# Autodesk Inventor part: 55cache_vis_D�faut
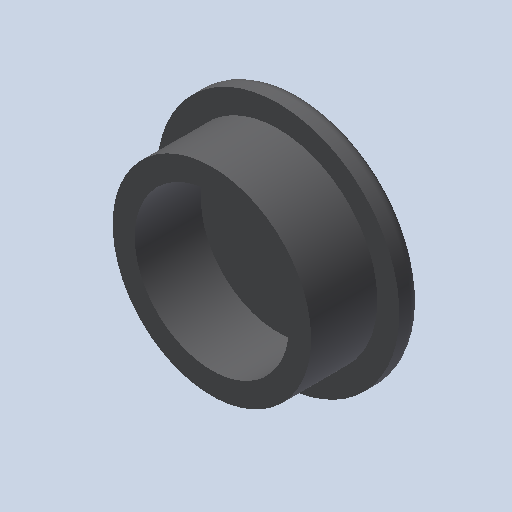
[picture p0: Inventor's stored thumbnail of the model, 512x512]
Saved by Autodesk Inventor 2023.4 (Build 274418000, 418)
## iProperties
Created: 2011-01
Part Number: 55cache_vis_D�faut
Document SubType Name: Modeling
Designer: eric
Density: 1 g/cm^3
Mass: 1.34892 g
Surface Area: 14.7157 cm^2
Volume: 1.34892 cm^3
Material: Générique
Appearance: Red
Author: eric
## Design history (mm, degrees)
feature "Base1"
node "Corps solides"
node "Corps surfaciques"
node "Solide1"
